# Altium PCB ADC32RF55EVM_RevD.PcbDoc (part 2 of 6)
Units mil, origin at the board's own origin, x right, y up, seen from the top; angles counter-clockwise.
Board outline 4190 x 2750 mil, 14 copper layers (Top Copper, Layer 2 (GND1), Layer 3 (PWR1), Layer 4 (GND2, Layer 5 (PWR2), Layer 6 (GND3), Layer 7 (SIG1), Layer 8 (GND4), Layer 9 (GND5), Layer 10 (SIG2), Layer 11 (GND6), Layer 12 (PWR3), Layer 13 (GND7), Bottom Copper), stack 58.6 mil thick; 427 components, 558 nets, 1902 pads, 1008 vias.
Unrouted connection lines stored in the file: 51.
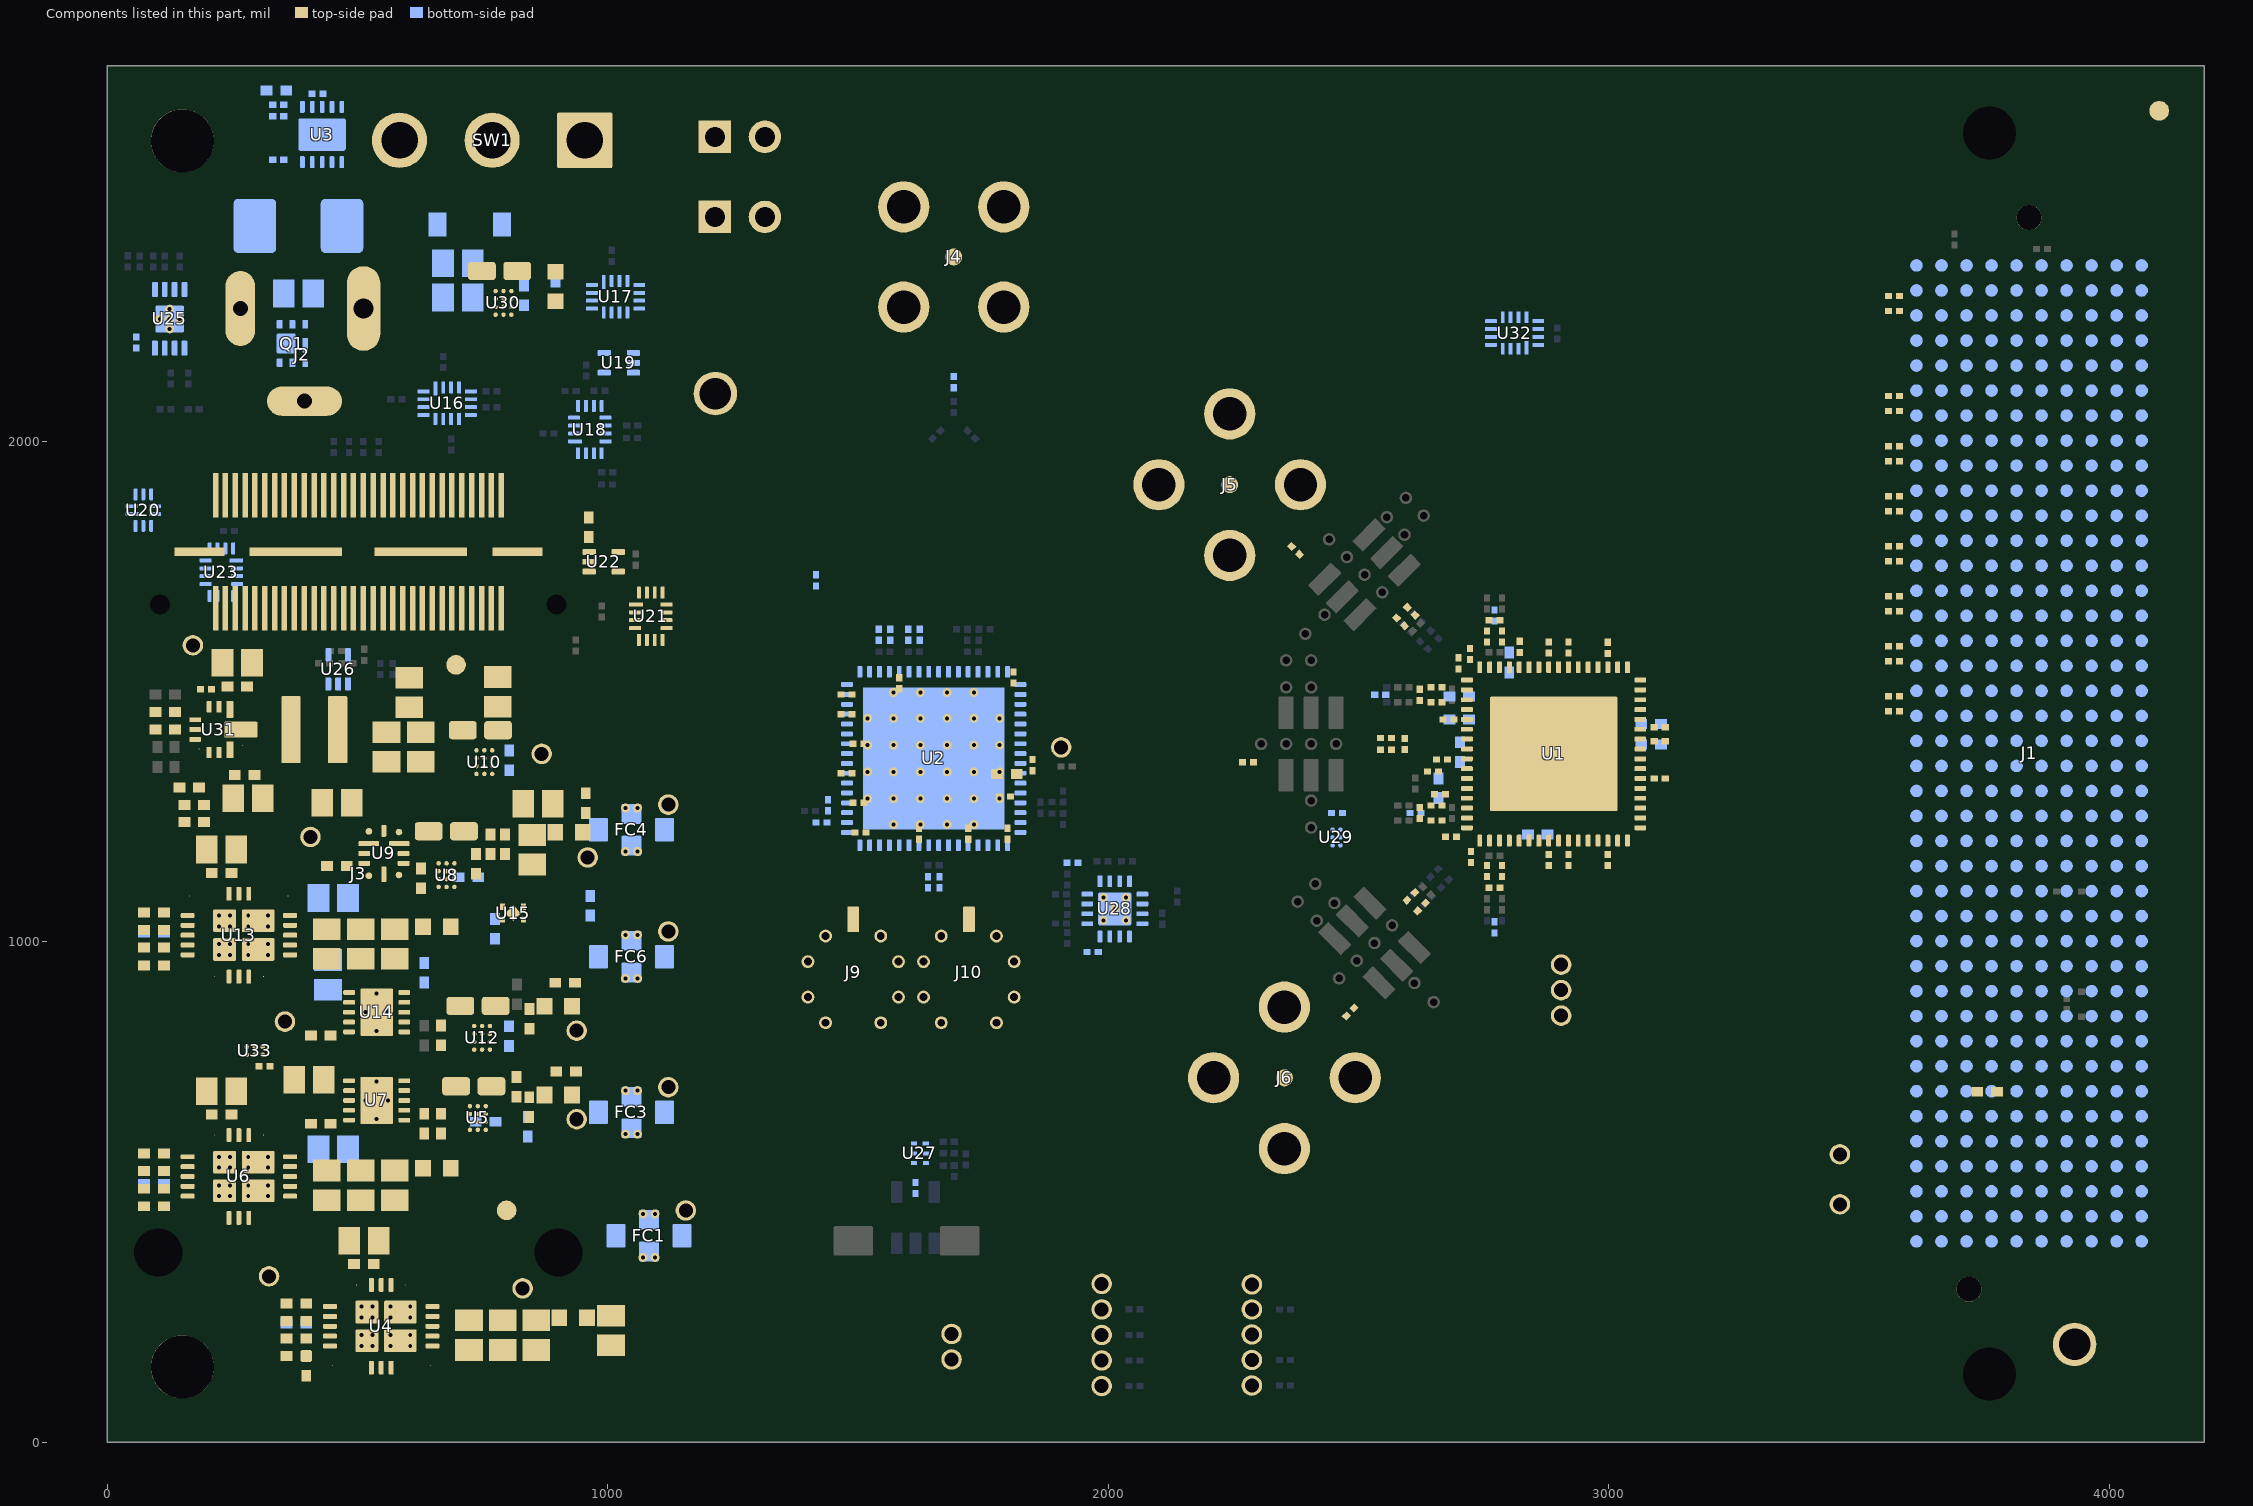
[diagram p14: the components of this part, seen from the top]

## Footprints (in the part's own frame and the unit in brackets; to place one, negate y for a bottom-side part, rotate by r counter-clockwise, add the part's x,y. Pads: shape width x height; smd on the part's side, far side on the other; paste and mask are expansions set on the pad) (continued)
DQK0006C [mm] "WSON"
  rrect50% 0.7x0.29 on Bottom Paste: 0(0.095,-0.65)
  rrect50% 0.9x0.86 on Bottom Paste: 0_1(0,0.325)
  rrect33% 0.45x0.3 smd: 1(-0.975,0.65) 2(-0.975,0) 3(-0.975,-0.65) 4(0.975,-0.65) 5(0.975,0) 6(0.975,0.65)
  rrect33% 0.75x0.3 smd paste-0.15: 7(0.095,-0.65)
  rrect11% 1x0.95 smd paste-0.5: 8(0,0.325)
  silkscreen extent -1.15,-1.15 1.15,1.15, body extent -1,-1 1,1, height 0.82
DQN0004A [mm]
  rect 0.25x0.31 smd paste-0.142 mask-0.14: 1(-0.535,0.325) 2(-0.535,-0.325) 3(0.535,-0.325) 4(0.535,0.325)
  rect 0.58x0.58 smd rot 45 paste-0.065 mask-0.051: 5(0,0)
  Top Copper region: 0.66,0.17 0.66,0.48 0.2,0.48 0.2,0.379 0.409,0.17
  Top Copper region: 0.66,-0.17 0.66,-0.48 0.2,-0.48 0.2,-0.379 0.409,-0.17
  Top Copper region: -0.66,-0.17 -0.66,-0.48 -0.2,-0.48 -0.2,-0.379 -0.409,-0.17
  Top Copper region: -0.66,0.17 -0.66,0.48 -0.2,0.48 -0.2,0.379 -0.409,0.17
  silkscreen extent -1.43,-0.7 0.88,0.7, body extent -0.5,-0.5 0.5,0.5, height 0.37
DRC0010J [mm] "VSON-10"
  rrect42% 0.6x0.24 smd: 1(-1.4,1) 2(-1.4,0.5) 3(-1.4,0) 4(-1.4,-0.5) 5(-1.4,-1) 6(1.4,-1) 7(1.4,-0.5) 8(1.4,0) 9(1.4,0.5) 10(1.4,1)
  rrect12% 1.65x2.4 smd paste-1 mask-2: 11(0,0)
  Top Copper region: -0.375,-1.65 -0.375,-1.2 -0.775,-1.2 -0.785,-1.2 -0.803,-1.192 -0.817,-1.178 -0.825,-1.16 -0.825,-1.15 -0.825,-1.15 -0.825,1.15 -0.825,1.16 -0.817,1.178 -0.803,1.192 -0.785,1.2 -0.775,1.2 -0.775,1.2 -0.375,1.2 -0.375,1.65 -0.375,1.66 -0.367,1.678 -0.353,1.692 -0.335,1.7 -0.325,1.7 -0.325,1.7 -0.325,1.7 -0.175,1.7 -0.165,1.7 -0.147,1.692 -0.133,1.678 -0.125,1.66 -0.125,1.65 -0.125,1.65 -0.125,1.2 0.125,1.2 0.125,1.65 0.125,1.66 0.133,1.678 0.147,1.692 0.165,1.7 0.175,1.7 0.175,1.7 0.175,1.7 0.325,1.7 0.335,1.7 0.353,1.692 0.367,1.678 0.375,1.66 0.375,1.65 0.375,1.65 0.375,1.2 0.775,1.2 0.785,1.2 0.803,1.192 0.817,1.178 0.825,1.16 0.825,1.15 0.825,1.15 0.825,-1.15 0.825,-1.16 0.817,-1.178 0.803,-1.192 0.785,-1.2 0.775,-1.2 0.775,-1.2 0.375,-1.2 0.375,-1.65 0.375,-1.66 0.367,-1.678 0.353,-1.692 0.335,-1.7 0.325,-1.7 0.325,-1.7 0.175,-1.7 0.165,-1.7 0.147,-1.692 0.133,-1.678 0.125,-1.66 0.125,-1.65 0.125,-1.65 0.125,-1.2 -0.125,-1.2 -0.125,-1.65 -0.125,-1.66 -0.133,-1.678 -0.147,-1.692 -0.165,-1.7 -0.175,-1.7 -0.175,-1.7 -0.325,-1.7 -0.335,-1.7 -0.353,-1.692 -0.367,-1.678 -0.375,-1.66 -0.375,-1.65
  body extent -1.5,-1.5 1.5,1.5, height 1
DRL0005A [mm] "SOTFL, 5-Flat Leads, Body 1.2x1.6x0.6mm, Pitch 0.5mm, TI recommended"
  rrect33% 0.67x0.3 smd mask+0.05: 1(-0.74,0.5) 2(-0.74,0) 3(-0.74,-0.5) 4(0.74,-0.5) 5(0.74,0.5)
  silkscreen extent -0.9,-0.95 0.5,0.95, body extent -0.8,-0.8 0.8,0.8, height 0.6
DRY0006A [mm]
  rrect20% 0.35x0.2 smd mask+0.05: 1(-0.298,0.5)
  rrect20% 0.3x0.2 smd mask+0.05: 2(-0.303,0) 3(-0.303,-0.5) 4(0.303,-0.5) 5(0.303,0) 6(0.303,0.5)
  silkscreen extent -0.76,0.64 -0.71,0.69, body extent -0.5,-0.72 0.5,0.72, height 0.6
DSC0010 [mm]
  rrect50% 0.6x0.24 smd paste+0 mask+0.07: 1(-1.4,1) 2(-1.4,0.5) 3(-1.4,0) 4(-1.4,-0.5) 5(-1.4,-1) 6(1.4,-1) 7(1.4,-0.5) 8(1.4,0) 9(1.4,0.5) 10(1.4,1)
  round 0.454 hole 0.2 mask+0.05: 11(-0.575,0) 11(0,-0.95) 11(0,0.95) 11(0.575,0)
  rrect6% 1.65x2.4 smd paste-1000 mask+0: 11(0,0)
  silkscreen extent -1.93,-1.55 1.55,1.55, body extent -1.8,-1.8 1.8,1.8, height 0.25
FCC_disclaimer [mil]
Fiducial10-20 [mm]
  round 1 smd paste-0.508 mask+0.203: 1(0,0)
FP-1101M2S3CGE2_SIP3-MFG [mm]
  rrect4% 2.8x2.8 hole 1.85 paste-2539.97 mask+0: 1(0,4.7)
  round 2.8 hole 1.85 paste-2539.97 mask+0: 2(0,0) 3(0,-4.7)
  silkscreen extent -3.3,-6.35 3.3,6.35, body extent -3.4,-6.45 3.4,6.45, height 0.25
FP-2116-440-AL_STANDOFF_HEX_1-4-MFG [mm]
  round 3.2 hole 3.2 unplated paste-2539.97 mask+0: ""(0,0)
  body extent -3.66,-3.18 3.66,3.18, height 31.88
FP-132134-15_CONN_SMA_JACK-MFG [mm]
  round 0.864 smd paste+0 mask+0: 1(0,0)
  round 2.6 hole 1.7 paste-2539.97 mask+0: 2(-2.54,2.54) 3(2.54,2.54) 4(-2.54,-2.54) 5(2.54,-2.54)
  silkscreen extent -3.6,-3.6 3.6,3.6, body extent -3.94,-3.94 3.94,3.94, height 0.25
FTDI_Dongle_001 [mm]
  rect 2.27x0.279 smd: 1(18.74,-7.25) 2(13.01,-7.25) 3(18.74,-6.75) 4(13.01,-6.75) 5(18.74,-6.25) 6(13.01,-6.25) 7(18.74,-5.75) 8(13.01,-5.75) 9(18.74,-5.25) 10(13.01,-5.25) 11(18.74,-4.75) 12(13.01,-4.75) 13(18.74,-4.25) 14(13.01,-4.25) 15(18.74,-3.75) 16(13.01,-3.75) 17(18.74,-3.25) 18(13.01,-3.25) 19(18.74,-2.75) 20(13.01,-2.75) 21(18.74,-2.25) 22(13.01,-2.25) 23(18.74,-1.75) 24(13.01,-1.75) 25(18.74,-1.25) 26(13.01,-1.25) 27(18.74,-0.75) 28(13.01,-0.75) 29(18.74,-0.25) 30(13.01,-0.25) 31(18.74,0.25) 32(13.01,0.25) 33(18.74,0.75) 34(13.01,0.75) 35(18.74,1.25) 36(13.01,1.25) 37(18.74,1.75) 38(13.01,1.75) 39(18.74,2.25) 40(13.01,2.25) 41(18.74,2.75) 42(13.01,2.75) 43(18.74,3.25) 44(13.01,3.25) 45(18.74,3.75) 46(13.01,3.75) 47(18.74,4.25) 48(13.01,4.25) 49(18.74,4.75) 50(13.01,4.75) 51(18.74,5.25) 52(13.01,5.25) 53(18.74,5.75) 54(13.01,5.75) 55(18.74,6.25) 56(13.01,6.25) 57(18.74,6.75) 58(13.01,6.75) 59(18.74,7.25) 60(13.01,7.25)
  round 2 hole 2.45 unplated: 4(-19.685,-10.16) 4(-19.685,10.16)
  round 0 hole 1.02 unplated: MH1(13.205,-10.065) MH2(13.205,10.065)
  rect 0.43x2.54 smd: MP1(15.875,-8.065) MP4(15.875,8.065)
  rect 0.43x4.7 smd: MP2(15.875,-3.175) MP3(15.875,3.175)
  silkscreen extent 12.26,-10.66 19.78,10.65, body extent -22.78,-12.7 22.22,12.7, height 10.54
Keystone5011 [mil] "Keystone Multipurpose loops"
  round 87 hole 63: 1(0,0)
  silkscreen extent -70,-70 70,70, body extent -63,-63 63,62, height 319
Label_650x200 [mil] "Thermal Transfer Label"
  round 1 on Mech13: 0(0,0)
  silkscreen extent -325,-100 325,100, body extent -325,-100 325,100, height 1
LED_LTST-C190-Green [mm] "Lite-On"
  rect 0.8x0.8 smd: 1(-0.75,0) 2(0.75,0)
  silkscreen extent -1.1,-0.8 1.8,0.8, body extent -0.85,-0.45 0.85,0.45, height 0.91
MMCNYN256 [mil] "Nylon Hex Nut 2-56"
  body extent -94,-108 94,108, height 256
Molex_0853050232 [mm] "Plug, 50 Ohm, Straight, SMT"
  rrect17% 0.6x1.3 smd: 1(0,0)
  round 0.654 hole 0.4 mask+0.05: 2(-2.3,-3.95) 2(-2.3,-2.15) 2(-1.4,-0.85) 2(-1.4,-5.25) 2(1.4,-5.25) 2(1.4,-0.85) 2(2.3,-3.95) 2(2.3,-2.15)
  round 0.025 smd: 2(0,-5.35)
  Top Copper pour cut-out: 0.998,-1.315 0.998,-0.45 -0.998,-0.45 -0.998,-1.321 -1.679,-1.973 -1.986,-2.865 -1.849,-3.798 -1.3,-4.565 -0.461,-4.995 0.482,-4.992 1.319,-4.557 1.864,-3.787 1.995,-2.854 1.683,-1.963 0.998,-1.315
  Top Copper pour cut-out: -0.33,0.699 -0.33,-0.698 0.33,-0.698 0.33,0.699
  Top Copper region: -2.6,-5.65 -2.6,-0.45 -1,-0.45 -1,-1.318 -1.732,-2.05 -2,-3.05 -1.732,-4.05 -1,-4.782 0,-5.05 1,-4.782 1.732,-4.05 2,-3.05 1.732,-2.05 1,-1.318 1,-1.318 1,-0.45 2.6,-0.45 2.6,-5.65
  Layer 2 (GND1) pour cut-out: 0.998,-1.315 0.998,-0.45 -0.998,-0.45 -0.998,-1.321 -1.679,-1.973 -1.986,-2.865 -1.849,-3.798 -1.3,-4.565 -0.461,-4.995 0.482,-4.992 1.319,-4.557 1.864,-3.787 1.995,-2.854 1.683,-1.963 0.998,-1.315
  Layer 2 (GND1) pour cut-out: 0.998,-1.315 0.998,-0.45 -0.998,-0.45 -0.998,-1.321 -1.679,-1.973 -1.986,-2.865 -1.849,-3.798 -1.3,-4.565 -0.461,-4.995 0.482,-4.992 1.319,-4.557 1.864,-3.787 1.995,-2.854 1.683,-1.963 0.998,-1.315
  Layer 2 (GND1) pour cut-out: 0.998,-1.315 0.998,-0.45 -0.998,-0.45 -0.998,-1.321 -1.679,-1.973 -1.986,-2.865 -1.849,-3.798 -1.3,-4.565 -0.461,-4.995 0.482,-4.992 1.319,-4.557 1.864,-3.787 1.995,-2.854 1.683,-1.963 0.998,-1.315
  Layer 2 (GND1) pour cut-out: -0.33,0.699 -0.33,-0.698 0.33,-0.698 0.33,0.699
  body extent -2.5,-5.55 2.5,0.45, height 4.1
NFM31PC [mm]
  rrect10% 0.95x1.2 smd paste+0: 1(-1.675,0) 3(1.675,0)
  round 0.2 / inner round 0.454 / far side round 0.454 hole 0.2 mask+0.05: 2(-0.305,-1.105) 2(-0.305,1.105) 2(0.305,-1.105) 2(0.305,1.105)
  rrect10% 1x1 smd paste+0: 2(0,-0.8) 2(0,0.8)
  body extent -1.7,-0.9 1.7,0.9, height 1.5
NKD0064A [mm] "QFN, 64-Leads, Body 9x9mm, Pitch 0.5mm"
  rrect40% 0.6x0.25 smd mask+0.07: 1(-4.4,3.75) 2(-4.4,3.25) 3(-4.4,2.75) 4(-4.4,2.25) 5(-4.4,1.75) 6(-4.4,1.25) 7(-4.4,0.75) 8(-4.4,0.25) 9(-4.4,-0.25) 10(-4.4,-0.75) 11(-4.4,-1.25) 12(-4.4,-1.75) 13(-4.4,-2.25) 14(-4.4,-2.75) 15(-4.4,-3.25) 16(-4.4,-3.75) 33(4.4,-3.75) 34(4.4,-3.25) 35(4.4,-2.75) 36(4.4,-2.25) 37(4.4,-1.75) 38(4.4,-1.25) 39(4.4,-0.75) 40(4.4,-0.25) 41(4.4,0.25) 42(4.4,0.75) 43(4.4,1.25) 44(4.4,1.75) 45(4.4,2.25) 46(4.4,2.75) 47(4.4,3.25) 48(4.4,3.75)
  rrect40% 0.25x0.6 smd mask+0.07: 17(-3.75,-4.4) 18(-3.25,-4.4) 19(-2.75,-4.4) 20(-2.25,-4.4) 21(-1.75,-4.4) 22(-1.25,-4.4) 23(-0.75,-4.4) 24(-0.25,-4.4) 25(0.25,-4.4) 26(0.75,-4.4) 27(1.25,-4.4) 28(1.75,-4.4) 29(2.25,-4.4) 30(2.75,-4.4) 31(3.25,-4.4) 32(3.75,-4.4) 49(3.75,4.4) 50(3.25,4.4) 51(2.75,4.4) 52(2.25,4.4) 53(1.75,4.4) 54(1.25,4.4) 55(0.75,4.4) 56(0.25,4.4) 57(-0.25,4.4) 58(-0.75,4.4) 59(-1.25,4.4) 60(-1.75,4.4) 61(-2.25,4.4) 62(-2.75,4.4) 63(-3.25,4.4) 64(-3.75,4.4)
  round 0.454 hole 0.2 mask+0.102: 65(-3.35,-2.04) 65(-3.35,-0.68) 65(-3.35,0.68) 65(-3.35,2.04) 65(-2.04,-3.35) 65(-2.04,-2.04) 65(-2.04,-0.68) 65(-2.04,0.68) 65(-2.04,2.04) 65(-2.04,3.35) 65(-0.68,-3.35) 65(-0.68,-2.04) 65(-0.68,-0.68) 65(-0.68,0.68) 65(-0.68,2.04) 65(-0.68,3.35) 65(0.68,-3.35) 65(0.68,-2.04) 65(0.68,-0.68) 65(0.68,0.68) 65(0.68,2.04) 65(0.68,3.35) 65(2.04,-3.35) 65(2.04,-2.04) 65(2.04,-0.68) 65(2.04,0.68) 65(2.04,2.04) 65(2.04,3.35) 65(3.35,-2.04) 65(3.35,-0.68) 65(3.35,0.68) 65(3.35,2.04)
  rrect1% 7.2x7.2 smd paste-3.6 mask+0.07: 65(0,0)
  silkscreen extent -4.65,-4.65 4.65,4.65, body extent -4.55,-4.55 4.55,4.55, height 0.81
PBC02SAAN [mm] "Sullins 100mil, 1x2, 230 mil above insulator"
  rect 1.65x1.65 hole 1.016: 1(0,1.27)
  round 1.65 hole 1.016: 2(0,-1.27)
  silkscreen extent -1.27,-2.54 1.6,2.54, body extent -1.27,-2.54 1.27,2.54, height 8.38
ProbePoint_TH_40mil [mil]
  round 41 hole 28: 1(0,0)
RAPC722X [mm] "Conn_DC Jack"
  oval 1.7x4.3 hole 1.01 slot 3.56 at 90 deg: 1(14.194,0)
  oval 1.5x3.8 hole 0.76 slot 3.05 at 90 deg: 2(7.946,0)
  oval 3.8x1.5 hole 0.76 slot 3.05 at 0 deg: 3(11.197,-4.7)
  silkscreen extent 0.2,-4.57 14.93,4.57, body extent 0.58,-4.97 15.06,4.56, height 10.92
RDU0028A [mm]
  round 0.025 smd mask+0.05: 1(-1.987,2.487) 2(-2.1,1.25) 6(-2.1,-1.25) 7(-1.987,-2.488) 13(1.987,-2.488) 14(2.1,-1.25) 18(2.1,1.25) 19(1.988,2.488)
  rrect40% 0.7x0.25 smd paste+0 mask+0.05: 3(-2.1,0.5) 4(-2.1,0) 5(-2.1,-0.5) 15(2.1,-0.5) 16(2.1,0) 17(2.1,0.5)
  rrect40% 0.25x0.7 smd paste+0 mask+0.05: 8(-1,-2.6) 9(-0.5,-2.6) 10(0,-2.6) 11(0.5,-2.6) 12(1,-2.6) 20(1,2.6) 21(0.5,2.6) 22(0,2.6) 23(-0.5,2.6) 24(-1,2.6)
  round 0.454 hole 0.2 mask+0.102: 25(-1,1) 25(-1,0.45) 25(-0.45,1) 25(-0.45,0.45) 26(-1,-0.475) 26(-1,-1.475) 26(-0.45,-0.475) 26(-0.45,-1.475) 27(0.45,-0.475) 27(0.45,-1.475) 27(1,-0.475) 27(1,-1.475) 28(0.45,1) 28(0.45,0.45) 28(1,1) 28(1,0.45)
  rrect9% 1.15x1.15 smd paste-1000 mask+0.05: 25(-0.725,0.725) 28(0.725,0.725)
  rrect9% 1.15x1.65 smd paste-1000 mask+0.05: 26(-0.725,-0.975) 27(0.725,-0.975)
  Top Copper region: 1.575,2.95 1.55,2.943 1.532,2.925 1.525,2.9 1.525,2.9 1.525,2.075 1.529,2.056 1.54,2.04 1.556,2.029 1.575,2.025 1.575,2.025 2.4,2.025 2.423,2.033 2.439,2.051 2.445,2.075 2.445,2.075 2.45,2.225 2.443,2.25 2.425,2.268 2.4,2.275 2.4,2.275 2.225,2.275 2.187,2.283 2.154,2.304 2.133,2.337 2.125,2.375 2.125,2.375 2.125,2.575 2.118,2.6 2.1,2.618 2.075,2.625 2.075,2.625 1.875,2.625 1.837,2.633 1.804,2.654 1.783,2.687 1.775,2.725 1.775,2.725 1.775,2.9 1.768,2.925 1.75,2.943 1.725,2.95 1.725,2.95
  Top Copper region: 2.4,-1.625 1.8,-1.625 1.775,-1.618 1.757,-1.6 1.75,-1.575 1.75,-1.575 1.75,-0.925 1.754,-0.906 1.765,-0.89 1.781,-0.879 1.8,-0.875 1.8,-0.875 2.4,-0.875 2.419,-0.879 2.435,-0.89 2.446,-0.906 2.45,-0.925 2.45,-0.925 2.45,-1.075 2.443,-1.1 2.425,-1.118 2.4,-1.125 2.4,-1.125 2.225,-1.125 2.187,-1.133 2.154,-1.154 2.133,-1.187 2.125,-1.225 2.125,-1.225 2.125,-1.275 2.138,-1.325 2.175,-1.362 2.225,-1.375 2.225,-1.375 2.4,-1.375 2.419,-1.379 2.435,-1.39 2.446,-1.406 2.45,-1.425 2.45,-1.425 2.45,-1.575 2.443,-1.6 2.425,-1.618 2.4,-1.625
  Top Copper region: 1.575,-2.95 1.55,-2.943 1.532,-2.925 1.525,-2.9 1.525,-2.9 1.525,-2.075 1.529,-2.056 1.54,-2.04 1.556,-2.029 1.575,-2.025 1.575,-2.025 2.4,-2.025 2.423,-2.033 2.439,-2.051 2.445,-2.075 2.445,-2.075 2.45,-2.225 2.443,-2.25 2.425,-2.268 2.4,-2.275 2.4,-2.275 2.225,-2.275 2.187,-2.283 2.154,-2.304 2.133,-2.337 2.125,-2.375 2.125,-2.375 2.125,-2.575 2.118,-2.6 2.1,-2.618 2.075,-2.625 2.075,-2.625 1.875,-2.625 1.837,-2.633 1.804,-2.654 1.783,-2.687 1.775,-2.725 1.775,-2.725 1.775,-2.9 1.768,-2.925 1.75,-2.943 1.725,-2.95 1.725,-2.95
  Top Copper region: -1.575,2.95 -1.55,2.943 -1.532,2.925 -1.525,2.9 -1.525,2.9 -1.525,2.075 -1.529,2.056 -1.54,2.04 -1.556,2.029 -1.575,2.025 -1.575,2.025 -2.4,2.025 -2.423,2.033 -2.439,2.051 -2.445,2.075 -2.445,2.075 -2.45,2.225 -2.443,2.25 -2.425,2.268 -2.4,2.275 -2.4,2.275 -2.225,2.275 -2.187,2.283 -2.154,2.304 -2.133,2.337 -2.125,2.375 -2.125,2.375 -2.125,2.575 -2.118,2.6 -2.1,2.618 -2.075,2.625 -2.075,2.625 -1.875,2.625 -1.837,2.633 -1.804,2.654 -1.783,2.687 -1.775,2.725 -1.775,2.725 -1.775,2.9 -1.768,2.925 -1.75,2.943 -1.725,2.95 -1.725,2.95
  Top Copper region: -1.575,-2.95 -1.55,-2.943 -1.532,-2.925 -1.525,-2.9 -1.525,-2.9 -1.525,-2.075 -1.529,-2.056 -1.54,-2.04 -1.556,-2.029 -1.575,-2.025 -1.575,-2.025 -2.4,-2.025 -2.423,-2.033 -2.439,-2.051 -2.445,-2.075 -2.445,-2.075 -2.45,-2.225 -2.443,-2.25 -2.425,-2.268 -2.4,-2.275 -2.4,-2.275 -2.225,-2.275 -2.187,-2.283 -2.154,-2.304 -2.133,-2.337 -2.125,-2.375 -2.125,-2.375 -2.125,-2.575 -2.118,-2.6 -2.1,-2.618 -2.075,-2.625 -2.075,-2.625 -1.875,-2.625 -1.837,-2.633 -1.804,-2.654 -1.783,-2.687 -1.775,-2.725 -1.775,-2.725 -1.775,-2.9 -1.768,-2.925 -1.75,-2.943 -1.725,-2.95 -1.725,-2.95
  Top Copper region: -2.4,-0.875 -1.8,-0.875 -1.775,-0.882 -1.757,-0.9 -1.75,-0.925 -1.75,-0.925 -1.75,-1.575 -1.754,-1.594 -1.765,-1.61 -1.781,-1.621 -1.8,-1.625 -1.8,-1.625 -2.4,-1.625 -2.419,-1.621 -2.435,-1.61 -2.446,-1.594 -2.45,-1.575 -2.45,-1.575 -2.45,-1.425 -2.443,-1.4 -2.425,-1.382 -2.4,-1.375 -2.4,-1.375 -2.225,-1.375 -2.187,-1.367 -2.154,-1.346 -2.133,-1.313 -2.125,-1.275 -2.125,-1.275 -2.125,-1.225 -2.138,-1.175 -2.175,-1.138 -2.225,-1.125 -2.225,-1.125 -2.4,-1.125 -2.419,-1.121 -2.435,-1.11 -2.446,-1.094 -2.45,-1.075 -2.45,-1.075 -2.45,-0.925 -2.443,-0.9 -2.425,-0.882 -2.4,-0.875
  Top Copper region: -2.4,1.625 -1.8,1.625 -1.781,1.621 -1.765,1.61 -1.754,1.594 -1.75,1.575 -1.75,1.575 -1.75,0.925 -1.754,0.906 -1.765,0.89 -1.781,0.879 -1.8,0.875 -1.8,0.875 -2.4,0.875 -2.419,0.879 -2.435,0.89 -2.446,0.906 -2.45,0.925 -2.45,0.925 -2.45,1.075 -2.443,1.1 -2.425,1.118 -2.4,1.125 -2.4,1.125 -2.225,1.125 -2.187,1.133 -2.154,1.154 -2.133,1.187 -2.125,1.225 -2.125,1.225 -2.125,1.275 -2.138,1.325 -2.175,1.362 -2.225,1.375 -2.225,1.375 -2.4,1.375 -2.419,1.379 -2.435,1.39 -2.446,1.406 -2.45,1.425 -2.45,1.425 -2.45,1.575 -2.443,1.6 -2.425,1.618 -2.4,1.625
  Top Copper region: 2.4,0.875 1.8,0.875 1.775,0.882 1.757,0.9 1.75,0.925 1.75,0.925 1.75,1.575 1.754,1.594 1.765,1.61 1.781,1.621 1.8,1.625 1.8,1.625 2.4,1.625 2.419,1.621 2.435,1.61 2.446,1.594 2.45,1.575 2.45,1.575 2.45,1.425 2.443,1.4 2.425,1.382 2.4,1.375 2.4,1.375 2.225,1.375 2.187,1.367 2.154,1.346 2.133,1.313 2.125,1.275 2.125,1.275 2.125,1.225 2.138,1.175 2.175,1.138 2.225,1.125 2.225,1.125 2.4,1.125 2.419,1.121 2.435,1.11 2.446,1.094 2.45,1.075 2.45,1.075 2.45,0.925 2.443,0.9 2.425,0.882 2.4,0.875
  silkscreen extent -3.2,-3.13 2.63,3.13, body extent -2.55,-3.05 2.55,3.05, height 0.25
RGT0016C [mm]
  rrect30% 0.6x0.24 smd paste+0 mask+0.07: 1(-1.4,0.75) 2(-1.4,0.25) 3(-1.4,-0.25) 4(-1.4,-0.75) 9(1.4,-0.75) 10(1.4,-0.25) 11(1.4,0.25) 12(1.4,0.75)
  rrect30% 0.24x0.6 smd paste+0 mask+0.07: 5(-0.75,-1.4) 6(-0.25,-1.4) 7(0.25,-1.4) 8(0.75,-1.4) 13(0.75,1.4) 14(0.25,1.4) 15(-0.25,1.4) 16(-0.75,1.4)
  round 0.454 hole 0.2 mask+0.05: 17(-0.58,-0.58) 17(-0.58,0.58) 17(0,0) 17(0.58,-0.58) 17(0.58,0.58)
  rrect10% 1.68x1.68 smd paste-0.065 mask+0.07: 17(0,0)
  silkscreen extent -1.97,-1.68 1.68,1.68, body extent -1.5,-1.5 1.5,1.5, height 1
RPS0012A-MFG [mm]
  round 0.34 smd paste+0 mask+0: 1(-0.761,1.127) 5(-0.761,-1.127)
  rrect40% 1.05x0.25 smd paste+0 mask+0: 2(-0.775,0.5) 10(0.775,0.5)
  rrect40% 0.6x0.25 smd paste+0 mask+0: 3(-1,0) 4(-1,-0.5) 8(1,-0.5) 9(1,0)
  rrect40% 0.25x0.8 smd paste+0 mask+0: 6(0,-1.05)
  round 0.332 smd paste+0 mask+0: 7(0.766,-1.091) 11(0.766,1.091)
  rrect40% 0.25x0.6 smd paste+0 mask+0: 12(0,1.15)
  Top Copper region: 1.25,-1.1 0.95,-1.1 0.95,-1.4 0.95,-1.41 0.942,-1.428 0.928,-1.442 0.91,-1.45 0.9,-1.45 0.9,-1.45 0.6,-1.45 0.59,-1.45 0.572,-1.442 0.558,-1.428 0.55,-1.41 0.55,-1.4 0.55,-1.4 0.55,-0.925 0.55,-0.915 0.558,-0.897 0.572,-0.883 0.59,-0.875 0.6,-0.875 0.6,-0.875 1.25,-0.875 1.26,-0.875 1.278,-0.883 1.292,-0.897 1.3,-0.915 1.3,-0.925 1.3,-0.925 1.3,-1.05 1.3,-1.06 1.292,-1.078 1.278,-1.092 1.26,-1.1 1.25,-1.1
  Top Copper region: -1.25,-1.1 -0.95,-1.1 -0.95,-1.4 -0.95,-1.41 -0.942,-1.428 -0.928,-1.442 -0.91,-1.45 -0.9,-1.45 -0.9,-1.45 -0.6,-1.45 -0.59,-1.45 -0.572,-1.442 -0.558,-1.428 -0.55,-1.41 -0.55,-1.4 -0.55,-1.4 -0.55,-0.925 -0.55,-0.915 -0.558,-0.897 -0.572,-0.883 -0.59,-0.875 -0.6,-0.875 -0.6,-0.875 -1.25,-0.875 -1.26,-0.875 -1.278,-0.883 -1.292,-0.897 -1.3,-0.915 -1.3,-0.925 -1.3,-0.925 -1.3,-1.05 -1.3,-1.06 -1.292,-1.078 -1.278,-1.092 -1.26,-1.1 -1.25,-1.1
  Top Copper region: -1.25,1.1 -0.95,1.1 -0.95,1.4 -0.95,1.41 -0.942,1.428 -0.928,1.442 -0.91,1.45 -0.9,1.45 -0.9,1.45 -0.6,1.45 -0.59,1.45 -0.572,1.442 -0.558,1.428 -0.55,1.41 -0.55,1.4 -0.55,1.4 -0.55,0.925 -0.55,0.915 -0.558,0.897 -0.572,0.883 -0.59,0.875 -0.6,0.875 -0.6,0.875 -1.25,0.875 -1.26,0.875 -1.278,0.883 -1.292,0.897 -1.3,0.915 -1.3,0.925 -1.3,0.925 -1.3,1.05 -1.3,1.06 -1.292,1.078 -1.278,1.092 -1.26,1.1 -1.25,1.1
  Top Copper region: 1.25,1.1 0.95,1.1 0.95,1.4 0.95,1.41 0.942,1.428 0.928,1.442 0.91,1.45 0.9,1.45 0.9,1.45 0.6,1.45 0.59,1.45 0.572,1.442 0.558,1.428 0.55,1.41 0.55,1.4 0.55,1.4 0.55,0.925 0.55,0.915 0.558,0.897 0.572,0.883 0.59,0.875 0.6,0.875 0.6,0.875 1.25,0.875 1.26,0.875 1.278,0.883 1.292,0.897 1.3,0.915 1.3,0.925 1.3,0.925 1.3,1.05 1.3,1.06 1.292,1.078 1.278,1.092 1.26,1.1 1.25,1.1
  silkscreen extent -1.41,-1.8 1.3,2.29, body extent -1.1,-1.25 1.1,1.25, height 1
RPY0014A [mm]
  round 0.025 smd mask+0.05: 1(-1.213,0.987) 5(-1.212,-0.988) 9(0.975,-0.8) 11(0.975,0.8)
  rrect20% 0.575x0.25 smd paste+0 mask+0.05: 2(-1.412,0.5) 3(-1.412,0) 4(-1.412,-0.5)
  rrect20% 0.25x0.575 smd paste+0 mask+0.05: 6(-0.7,-1.162) 7(-0.2,-1.162) 13(-0.2,1.162) 14(-0.7,1.162)
  rrect10% 0.35x0.851 smd paste+0 mask+0.05: 8(0.35,-1.025) 12(0.35,1.025)
  rrect10% 1.675x0.8 smd paste-0.825 mask-0.826: 10(0.913,0)
  Top Copper region: 1.237,0.6 1.65,0.6 1.669,0.604 1.685,0.615 1.696,0.631 1.7,0.65 1.7,0.65 1.7,0.95 1.696,0.969 1.685,0.985 1.669,0.996 1.65,1 1.65,1 1.175,1 1.175,1.4 1.175,1.4 1.175,1.4 1.171,1.419 1.16,1.435 1.144,1.446 1.125,1.45 1.125,1.45 0.82,1.45 0.803,1.447 0.788,1.437 0.778,1.422 0.775,1.405 0.775,1.405 0.775,0.64 0.778,0.625 0.787,0.612 0.8,0.603 0.815,0.6 0.815,0.6 0.874,0.6
  Top Copper region: 1.237,-0.6 1.65,-0.6 1.669,-0.604 1.685,-0.615 1.696,-0.631 1.7,-0.65 1.7,-0.65 1.7,-0.95 1.696,-0.969 1.685,-0.985 1.669,-0.996 1.65,-1 1.65,-1 1.175,-1 1.175,-1.4 1.175,-1.4 1.175,-1.4 1.171,-1.419 1.16,-1.435 1.144,-1.446 1.125,-1.45 1.125,-1.45 0.82,-1.45 0.803,-1.447 0.788,-1.437 0.778,-1.422 0.775,-1.405 0.775,-1.405 0.775,-0.64 0.778,-0.625 0.787,-0.612 0.8,-0.603 0.815,-0.6 0.815,-0.6 0.874,-0.6
  Top Copper region: -1.115,0.875 -1.1,0.878 -1.087,0.887 -1.078,0.9 -1.075,0.915 -1.075,0.915 -1.075,1.4 -1.075,1.4 -1.075,1.405 -1.078,1.422 -1.088,1.437 -1.103,1.447 -1.12,1.45 -1.12,1.45 -1.3,1.45 -1.319,1.446 -1.335,1.435 -1.346,1.419 -1.35,1.4 -1.35,1.4 -1.35,1.1 -1.655,1.1 -1.672,1.097 -1.687,1.087 -1.697,1.072 -1.7,1.055 -1.7,1.055 -1.7,0.915 -1.697,0.9 -1.688,0.887 -1.675,0.878 -1.66,0.875 -1.66,0.875
  Top Copper region: -1.115,-0.875 -1.1,-0.878 -1.087,-0.887 -1.078,-0.9 -1.075,-0.915 -1.075,-0.915 -1.075,-1.4 -1.075,-1.4 -1.075,-1.405 -1.078,-1.422 -1.088,-1.437 -1.103,-1.447 -1.12,-1.45 -1.12,-1.45 -1.3,-1.45 -1.319,-1.446 -1.335,-1.435 -1.346,-1.419 -1.35,-1.4 -1.35,-1.4 -1.35,-1.1 -1.655,-1.1 -1.672,-1.097 -1.687,-1.087 -1.696,-1.072 -1.7,-1.055 -1.7,-1.055 -1.7,-0.915 -1.697,-0.9 -1.688,-0.887 -1.675,-0.878 -1.66,-0.875 -1.66,-0.875
  silkscreen extent -2.4,-1.63 1.92,1.63, body extent -1.5,-1.25 1.5,1.25, height 1.01
RSV0016A [mm] "QFN, 16-Leads, Body 1.8x2.6mm, Pitch 0.4mm, TI Recommended"
  rrect25% 0.7x0.2 smd mask+0.05: 1(-0.75,0.6)
  rrect25% 0.6x0.2 smd mask+0.05: 2(-0.8,0.2) 3(-0.8,-0.2) 4(-0.8,-0.6) 9(0.8,-0.6) 10(0.8,-0.2) 11(0.8,0.2) 12(0.8,0.6)
  rrect25% 0.2x0.6 smd mask+0.05: 5(-0.6,-1.2) 6(-0.2,-1.2) 7(0.2,-1.2) 8(0.6,-1.2) 13(0.6,1.2) 14(0.2,1.2) 15(-0.2,1.2) 16(-0.6,1.2)
  silkscreen extent -1.08,-1.33 1.08,1.45, body extent -0.93,-1.32 0.92,1.33, height 0.56
RSW0010A [mm]
  rrect50% 0.7x0.2 smd mask+0.05: 1(-0.55,0.2)
  rrect50% 0.6x0.2 smd mask+0.05: 2(-0.6,-0.2) 6(0.6,-0.2) 7(0.6,0.2)
  rrect50% 0.2x0.6 smd mask+0.05: 3(-0.4,-0.8) 4(0,-0.8) 5(0.4,-0.8) 8(0.4,0.8) 9(0,0.8) 10(-0.4,0.8)
  silkscreen extent -0.87,-0.92 0.72,0.93, body extent -0.7,-0.9 0.7,0.9, height 0.55
RTD0064L [mm] "VQFN-64"
  rrect40% 0.6x0.25 smd: 1(-4.4,3.75) 2(-4.4,3.25) 3(-4.4,2.75) 4(-4.4,2.25) 5(-4.4,1.75) 6(-4.4,1.25) 7(-4.4,0.75) 8(-4.4,0.25) 9(-4.4,-0.25) 10(-4.4,-0.75) 11(-4.4,-1.25) 12(-4.4,-1.75) 13(-4.4,-2.25) 14(-4.4,-2.75) 15(-4.4,-3.25) 16(-4.4,-3.75) 33(4.4,-3.75) 34(4.4,-3.25) 35(4.4,-2.75) 36(4.4,-2.25) 37(4.4,-1.75) 38(4.4,-1.25) 39(4.4,-0.75) 40(4.4,-0.25) 41(4.4,0.25) 42(4.4,0.75) 43(4.4,1.25) 44(4.4,1.75) 45(4.4,2.25) 46(4.4,2.75) 47(4.4,3.25) 48(4.4,3.75)
  rrect40% 0.25x0.6 smd: 17(-3.75,-4.4) 18(-3.25,-4.4) 19(-2.75,-4.4) 20(-2.25,-4.4) 21(-1.75,-4.4) 22(-1.25,-4.4) 23(-0.75,-4.4) 24(-0.25,-4.4) 25(0.25,-4.4) 26(0.75,-4.4) 27(1.25,-4.4) 28(1.75,-4.4) 29(2.25,-4.4) 30(2.75,-4.4) 31(3.25,-4.4) 32(3.75,-4.4) 49(3.75,4.4) 50(3.25,4.4) 51(2.75,4.4) 52(2.25,4.4) 53(1.75,4.4) 54(1.25,4.4) 55(0.75,4.4) 56(0.25,4.4) 57(-0.25,4.4) 58(-0.75,4.4) 59(-1.25,4.4) 60(-1.75,4.4) 61(-2.25,4.4) 62(-2.75,4.4) 63(-3.25,4.4) 64(-3.75,4.4)
  rrect2% 5.808x6.466 smd paste-3.5: 65(0,0)
  silkscreen extent -5.83,3.53 -5.13,4.23, body extent -4.5,-4.5 4.5,4.5, height 0.9
SAMTEC_ASP-134488-01 [mm]
  round 0.64 smd far side paste+0.125: A1(24.79,-5.715) A2(23.52,-5.715) A3(22.25,-5.715) A4(20.98,-5.715) A5(19.71,-5.715) A6(18.44,-5.715) A7(17.17,-5.715) A8(15.9,-5.715) A9(14.63,-5.715) A10(13.36,-5.715) A11(12.09,-5.715) A12(10.82,-5.715) A13(9.55,-5.715) A14(8.28,-5.715) A15(7.01,-5.715) A16(5.74,-5.715) A17(4.47,-5.715) A18(3.2,-5.715) A19(1.93,-5.715) A20(0.66,-5.715) A21(-0.61,-5.715) A22(-1.88,-5.715) A23(-3.15,-5.715) A24(-4.42,-5.715) A25(-5.69,-5.715) A26(-6.96,-5.715) A27(-8.23,-5.715) A28(-9.5,-5.715) A29(-10.77,-5.715) A30(-12.04,-5.715) A31(-13.31,-5.715) A32(-14.58,-5.715) A33(-15.85,-5.715) A34(-17.12,-5.715) A35(-18.39,-5.715) A36(-19.66,-5.715) A37(-20.93,-5.715) A38(-22.2,-5.715) A39(-23.47,-5.715) A40(-24.74,-5.715) B1(24.79,-4.445) B2(23.52,-4.445) B3(22.25,-4.445) B4(20.98,-4.445) B5(19.71,-4.445) B6(18.44,-4.445) B7(17.17,-4.445) B8(15.9,-4.445) B9(14.63,-4.445) B10(13.36,-4.445) B11(12.09,-4.445) B12(10.82,-4.445) B13(9.55,-4.445) B14(8.28,-4.445) B15(7.01,-4.445) B16(5.74,-4.445) B17(4.47,-4.445) B18(3.2,-4.445) B19(1.93,-4.445) B20(0.66,-4.445) B21(-0.61,-4.445) B22(-1.88,-4.445) B23(-3.15,-4.445) B24(-4.42,-4.445) B25(-5.69,-4.445) B26(-6.96,-4.445) B27(-8.23,-4.445) B28(-9.5,-4.445) B29(-10.77,-4.445) B30(-12.04,-4.445) B31(-13.31,-4.445) B32(-14.58,-4.445) B33(-15.85,-4.445) B34(-17.12,-4.445) B35(-18.39,-4.445) B36(-19.66,-4.445) B37(-20.93,-4.445) B38(-22.2,-4.445) B39(-23.47,-4.445) B40(-24.74,-4.445) C1(24.79,-3.175) C2(23.52,-3.175) C3(22.25,-3.175) C4(20.98,-3.175) C5(19.71,-3.175) C6(18.44,-3.175) C7(17.17,-3.175) C8(15.9,-3.175) C9(14.63,-3.175) C10(13.36,-3.175) C11(12.09,-3.175) C12(10.82,-3.175) C13(9.55,-3.175) C14(8.28,-3.175) C15(7.01,-3.175) C16(5.74,-3.175) C17(4.47,-3.175) C18(3.2,-3.175) C19(1.93,-3.175) C20(0.66,-3.175) C21(-0.61,-3.175) C22(-1.88,-3.175) C23(-3.15,-3.175) C24(-4.42,-3.175) C25(-5.69,-3.175) C26(-6.96,-3.175) C27(-8.23,-3.175) C28(-9.5,-3.175) C29(-10.77,-3.175) C30(-12.04,-3.175) C31(-13.31,-3.175) C32(-14.58,-3.175) C33(-15.85,-3.175) C34(-17.12,-3.175) C35(-18.39,-3.175) C36(-19.66,-3.175) C37(-20.93,-3.175) C38(-22.2,-3.175) C39(-23.47,-3.175) C40(-24.74,-3.175) D1(24.79,-1.905) D2(23.52,-1.905) D3(22.25,-1.905) D4(20.98,-1.905) D5(19.71,-1.905) D6(18.44,-1.905) D7(17.17,-1.905) D8(15.9,-1.905) D9(14.63,-1.905) D10(13.36,-1.905) D11(12.09,-1.905) D12(10.82,-1.905) D13(9.55,-1.905) D14(8.28,-1.905) D15(7.01,-1.905) D16(5.74,-1.905) D17(4.47,-1.905) D18(3.2,-1.905) D19(1.93,-1.905) D20(0.66,-1.905) D21(-0.61,-1.905) D22(-1.88,-1.905) D23(-3.15,-1.905) D24(-4.42,-1.905) D25(-5.69,-1.905) D26(-6.96,-1.905) D27(-8.23,-1.905) D28(-9.5,-1.905) D29(-10.77,-1.905) D30(-12.04,-1.905) D31(-13.31,-1.905) D32(-14.58,-1.905) D33(-15.85,-1.905) D34(-17.12,-1.905) D35(-18.39,-1.905) D36(-19.66,-1.905) D37(-20.93,-1.905) D38(-22.2,-1.905) D39(-23.47,-1.905) D40(-24.74,-1.905) E1(24.79,-0.635) E2(23.52,-0.635) E3(22.25,-0.635) E4(20.98,-0.635) E5(19.71,-0.635) E6(18.44,-0.635) E7(17.17,-0.635) E8(15.9,-0.635) E9(14.63,-0.635) E10(13.36,-0.635) E11(12.09,-0.635) E12(10.82,-0.635) E13(9.55,-0.635) E14(8.28,-0.635) E15(7.01,-0.635) E16(5.74,-0.635) E17(4.47,-0.635) E18(3.2,-0.635) E19(1.93,-0.635) E20(0.66,-0.635) E21(-0.61,-0.635) E22(-1.88,-0.635) E23(-3.15,-0.635) E24(-4.42,-0.635) E25(-5.69,-0.635) E26(-6.96,-0.635) E27(-8.23,-0.635) E28(-9.5,-0.635) E29(-10.77,-0.635) E30(-12.04,-0.635) E31(-13.31,-0.635) E32(-14.58,-0.635) E33(-15.85,-0.635) E34(-17.12,-0.635) E35(-18.39,-0.635) E36(-19.66,-0.635) E37(-20.93,-0.635) E38(-22.2,-0.635) E39(-23.47,-0.635) E40(-24.74,-0.635) F1(24.79,0.635) F2(23.52,0.635) F3(22.25,0.635) F4(20.98,0.635) F5(19.71,0.635) F6(18.44,0.635) F7(17.17,0.635) F8(15.9,0.635) F9(14.63,0.635) F10(13.36,0.635) F11(12.09,0.635) F12(10.82,0.635) F13(9.55,0.635) F14(8.28,0.635) F15(7.01,0.635) F16(5.74,0.635) F17(4.47,0.635) F18(3.2,0.635) F19(1.93,0.635) F20(0.66,0.635) F21(-0.61,0.635) F22(-1.88,0.635) F23(-3.15,0.635) F24(-4.42,0.635) F25(-5.69,0.635) F26(-6.96,0.635) F27(-8.23,0.635) F28(-9.5,0.635) F29(-10.77,0.635) F30(-12.04,0.635) F31(-13.31,0.635) F32(-14.58,0.635) F33(-15.85,0.635) F34(-17.12,0.635) F35(-18.39,0.635) F36(-19.66,0.635) F37(-20.93,0.635) F38(-22.2,0.635) F39(-23.47,0.635) F40(-24.74,0.635) G1(24.79,1.905) G2(23.52,1.905) G3(22.25,1.905) G4(20.98,1.905) G5(19.71,1.905) G6(18.44,1.905) G7(17.17,1.905) G8(15.9,1.905) G9(14.63,1.905) G10(13.36,1.905) G11(12.09,1.905) G12(10.82,1.905) G13(9.55,1.905) G14(8.28,1.905) G15(7.01,1.905) G16(5.74,1.905) G17(4.47,1.905) G18(3.2,1.905) G19(1.93,1.905) G20(0.66,1.905) G21(-0.61,1.905) G22(-1.88,1.905) G23(-3.15,1.905) G24(-4.42,1.905) G25(-5.69,1.905) G26(-6.96,1.905) G27(-8.23,1.905) G28(-9.5,1.905) G29(-10.77,1.905) G30(-12.04,1.905) G31(-13.31,1.905) G32(-14.58,1.905) G33(-15.85,1.905) G34(-17.12,1.905) G35(-18.39,1.905) G36(-19.66,1.905) G37(-20.93,1.905) G38(-22.2,1.905) G39(-23.47,1.905) G40(-24.74,1.905) H1(24.79,3.175) H2(23.52,3.175) H3(22.25,3.175) H4(20.98,3.175) H5(19.71,3.175) H6(18.44,3.175) H7(17.17,3.175) H8(15.9,3.175) H9(14.63,3.175) H10(13.36,3.175) H11(12.09,3.175) H12(10.82,3.175) H13(9.55,3.175) H14(8.28,3.175) H15(7.01,3.175) H16(5.74,3.175) H17(4.47,3.175) H18(3.2,3.175) H19(1.93,3.175) H20(0.66,3.175) H21(-0.61,3.175) H22(-1.88,3.175) H23(-3.15,3.175) H24(-4.42,3.175) H25(-5.69,3.175) H26(-6.96,3.175) H27(-8.23,3.175) H28(-9.5,3.175) H29(-10.77,3.175) H30(-12.04,3.175) H31(-13.31,3.175) H32(-14.58,3.175) H33(-15.85,3.175) H34(-17.12,3.175) H35(-18.39,3.175) H36(-19.66,3.175) H37(-20.93,3.175) H38(-22.2,3.175) H39(-23.47,3.175) H40(-24.74,3.175) J1(24.79,4.445) J2(23.52,4.445) J3(22.25,4.445) J4(20.98,4.445) J5(19.71,4.445) J6(18.44,4.445) J7(17.17,4.445) J8(15.9,4.445) J9(14.63,4.445) J10(13.36,4.445) J11(12.09,4.445) J12(10.82,4.445) J13(9.55,4.445) J14(8.28,4.445) J15(7.01,4.445) J16(5.74,4.445) J17(4.47,4.445) J18(3.2,4.445) J19(1.93,4.445) J20(0.66,4.445) J21(-0.61,4.445) J22(-1.88,4.445) J23(-3.15,4.445) J24(-4.42,4.445) J25(-5.69,4.445) J26(-6.96,4.445) J27(-8.23,4.445) J28(-9.5,4.445) J29(-10.77,4.445) J30(-12.04,4.445) J31(-13.31,4.445) J32(-14.58,4.445) J33(-15.85,4.445) J34(-17.12,4.445) J35(-18.39,4.445) J36(-19.66,4.445) J37(-20.93,4.445) J38(-22.2,4.445) J39(-23.47,4.445) J40(-24.74,4.445) K1(24.79,5.715) K2(23.52,5.715) K3(22.25,5.715) K4(20.98,5.715) K5(19.71,5.715) K6(18.44,5.715) K7(17.17,5.715) K8(15.9,5.715) K9(14.63,5.715) K10(13.36,5.715) K11(12.09,5.715) K12(10.82,5.715) K13(9.55,5.715) K14(8.28,5.715) K15(7.01,5.715) K16(5.74,5.715) K17(4.47,5.715) K18(3.2,5.715) K19(1.93,5.715) K20(0.66,5.715) K21(-0.61,5.715) K22(-1.88,5.715) K23(-3.15,5.715) K24(-4.42,5.715) K25(-5.69,5.715) K26(-6.96,5.715) K27(-8.23,5.715) K28(-9.5,5.715) K29(-10.77,5.715) K30(-12.04,5.715) K31(-13.31,5.715) K32(-14.58,5.715) K33(-15.85,5.715) K34(-17.12,5.715) K35(-18.39,5.715) K36(-19.66,5.715) K37(-20.93,5.715) K38(-22.2,5.715) K39(-23.47,5.715) K40(-24.74,5.715)
  round 0 hole 2.69 unplated: ""(-31.471,2.007) ""(31.521,2.007)
  round 1.27 hole 1.27 unplated: ""(-27.166,3.05) ""(27.216,0)
  body extent -27.86,-7.34 28.81,7.34, height 7.11
SMBJ15CA [mil]
  rrect20% 85x107.99 smd: 1(-87.01,0) 2(87.01,0)
  silkscreen extent -125,-79 125,79, body extent -104,-73 104,73, height 89
SOD-123 [mm] "On Semi recommended land pattern"
  rect 0.915x1.22 smd: 1(-1.637,0) 2(1.637,0)
  silkscreen extent -2.74,-1.17 2.03,1.17, body extent -1.93,-0.9 1.93,0.9, height 1.35
SPC02SYAN [mil] "SULLINS"
  round 1 on Mech3: 0(0,0)
  body extent -98,-47 99,47, height 366
TDFN8 [mm]
  rrect30% 0.75x0.3 smd paste+0 mask+0.05: 1(-1.5,0.75) 2(-1.5,0.25) 3(-1.5,-0.25) 4(-1.5,-0.75) 5(1.478,-0.75) 6(1.478,-0.25) 7(1.478,0.25) 8(1.478,0.75)
  round 0.327 / inner round 0.454 / far side round 0.454 hole 0.2 mask+0.05: 9(-0.5,0) 9(0,-0.5) 9(0,0) 9(0,0.5) 9(0.5,0)
  rrect10% 1.36x1.46 smd paste+0 mask+0.05: 9(0,0)
  silkscreen extent -2.23,0.67 -2.14,0.83, body extent -1.5,-1 1.5,1, height 0.76
TI_Stacked_Overlay_Medium [mil]
  silkscreen extent -576,-136 576,135
WEEE_Minimum [mil] "WEEElie bin"
  silkscreen extent -95,-172 99,104
XGL4020 [mm]
  rrect10% 0.98x3.4 smd paste+0 mask+0: 1(-1.185,0) 2(1.185,0)
  silkscreen extent -2.67,-2.15 2.15,2.15, body extent -2.25,-2.25 2.25,2.25, height 0.25
YBG0006AJAP [mm] "DSBGA-6"
  round 0.23 smd paste-0.23 mask+0.032: A1(-0.2,0.4) A2(0.2,0.4) B1(-0.2,0) B2(0.2,0) C1(-0.2,-0.4) C2(0.2,-0.4)
  body extent -0.61,-0.81 0.62,0.82, height 0.5
YFF0012AKAD [mm] "TI DSBGA 1.675x1.418mm"
  round 0.225 smd paste-0.13 mask+0: A1(-0.4,0.6) A2(0,0.6) A3(0.4,0.6) B1(-0.4,0.2) B2(0,0.2) B3(0.4,0.2) C1(-0.4,-0.2) C2(0,-0.2) C3(0.4,-0.2) D1(-0.4,-0.6) D2(0,-0.6) D3(0.4,-0.6)
  silkscreen extent -0.8,-0.92 0.8,0.92, body extent -0.71,-0.84 0.71,0.84, height 0.63

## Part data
C1 C18 C32 C40 C51: library part capcc01380, "CAP CER 0.1UF 25V X7R 0402", Manufacturer="KYOCERA AVX", Operating Temperature="-55°C ~ 125°C", Ratings=-, Supplier Part Number 1=478-10050-1-ND, Temperature Coefficient=X7R, Tolerance=±5%, Voltage - Rated=25V
C2 C3 C4: library part capcc02687, "CAP CER 1UF 50V X7R 0805", Manufacturer="TDK Corporation", Operating Temperature="-55°C ~ 125°C", Ratings=-, Supplier Part Number 1=445-7547-1-ND, Temperature Coefficient=X7R, Tolerance=±10%, Voltage - Rated=50V
C5 C6: library part capcc03754, "CAP CER 1000PF 25V X7R 0201", Manufacturer="KYOCERA AVX", Operating Temperature="-55°C ~ 125°C", Ratings=-, Supplier Part Number 1=478-13000-1-ND, Temperature Coefficient=X7R, Tolerance=±10%, Voltage - Rated=25V
C7 C19 C52 C165 C177: library part capcc03511, "CAP CER 10UF 25V X7S 0805", Manufacturer="TDK Corporation", Operating Temperature="-55°C ~ 125°C", Ratings=-, Supplier Part Number 1=445-181600-1-ND, Temperature Coefficient=X7S, Tolerance=±10%, Voltage - Rated=25V
C8 C20 C53 C166 C178: library part capcc04216, "CAP CER 2200PF 50V X7R 0402", Manufacturer="KYOCERA AVX", Operating Temperature="-55°C ~ 125°C", Ratings=-, Supplier Part Number 1=478-5131-1-ND, Temperature Coefficient=X7R, Tolerance=±5%, Voltage - Rated=50V
C9 C10 C11 C12 C13 C14 C16 C17 C21 C22 C23 C24 C25 C41 C42 C43 C46 C54 C55 C56 C57: library part capcc09395, "CAP CER 22UF 10V X7S 0805", Manufacturer="TDK Corporation", Operating Temperature="-55°C ~ 125°C", Ratings=-, Supplier Part Number 1=445-14560-1-ND, Temperature Coefficient=X7S, Tolerance=±20%, Voltage - Rated=10V
C15: library part capcc02208, "CAP CER 0.47UF 16V X7S 0402", Manufacturer="TDK Corporation", Operating Temperature="-55°C ~ 125°C", Ratings=AEC-Q200, Supplier Part Number 1=445-174214-1-ND, Temperature Coefficient=X7S, Tolerance=±10%, Voltage - Rated=16V
C26 C28 C59 C65 C91 C109 C110 C114 C115 C120 C122 C123 C149: library part capcc09406, "CAP CER 10UF 10V X5R 0402", Manufacturer="KYOCERA AVX", Operating Temperature="-55°C ~ 85°C", Ratings=-, Supplier Part Number 1=478-10052-1-ND, Temperature Coefficient=X5R, Tolerance=±20%, Voltage - Rated=10V
C27 C35 C39 C60: library part capcc02785, "CAP CER 1UF 35V X5R 0402", Manufacturer="TDK Corporation", Operating Temperature="-55°C ~ 85°C", Ratings=-, Supplier Part Number 1=445-175218-1-ND, Temperature Coefficient=X5R, Tolerance=±10%, Voltage - Rated=35V
C29 C30 C33: library part capcc03154, "CAP CER 2.2UF 16V X6S 0402", Manufacturer="TDK Corporation", Operating Temperature="-55°C ~ 105°C", Ratings=-, Supplier Part Number 1=445-9103-1-ND, Temperature Coefficient=X6S, Tolerance=±10%, Voltage - Rated=16V
C31 C64: library part capcc03139, "CAP CER 4.7UF 10V X5R 0402", Manufacturer="TDK Corporation", Operating Temperature="-55°C ~ 85°C", Ratings=-, Supplier Part Number 1=445-175214-1-ND, Temperature Coefficient=X5R, Tolerance=±10%, Voltage - Rated=10V
C34: library part capcc05466, "CAP CER 10000PF 50V X7R 0402", Manufacturer="KYOCERA AVX", Operating Temperature="-55°C ~ 125°C", Ratings=-, Supplier Part Number 1=478-04025C103MAT2ACT-ND, Temperature Coefficient=X7R, Tolerance=±20%, Voltage - Rated=50V
C44 C45 C50 C67 C71 C76 C82 C92 C107 C108 C111 C112 C113 C116 C117 C118 C119 C121 C124 C125 C126 C127 C128 C129 C130 C131 C132 C139 C140 C141 C142 C143 C144 C145 C146 C147 C148 C150 C151 C152 C156 C159 C160 C164: library part capcc01294, "CAP CER 0.1UF 25V X5R 0201", Manufacturer="TDK Corporation", Operating Temperature="-55°C ~ 85°C", Ratings=-, Supplier Part Number 1=445-13671-1-ND, Temperature Coefficient=X5R, Tolerance=±10%, Voltage - Rated=25V
C68 C74 C75 C78 C79 C154 C155 C158: library part capcc08427, "CAP CER 68PF 25V C0G/NP0 0201", Manufacturer="Murata Electronics", Operating Temperature="-55°C ~ 125°C", Ratings=-, Supplier Part Number 1=490-13322-1-ND, Temperature Coefficient="C0G, NP0", Tolerance=±1%, Voltage - Rated=25V
C69 C70 C73 C80 C81 C84 C85 C86 C87 C88 C89 C90 C93 C94 C95 C96 C97 C98 C99 C100 C101 C102 C103 C104 C105 C106 C133 C134 C135 C136 C137 C138 C153: library part 0201RFCaps0693, "Broadband Capacitors", Alt Manufacturer="Murata Electronics", Alt PartNumber=GRM033C71C104ME14D, Manufacturer="Passive Plus", Operating Temperature="-55°C ~ 125°C", Temperature Coefficient="C0G, NP0", Tolerance=±10%, Voltage - Rated=16V
C72 C77 C83 C157: library part capcc06867, "CAP CER 0.6PF 50V C0G/NP0 0201", Manufacturer="Murata Electronics", Operating Temperature="-55°C ~ 125°C", Ratings=-, Supplier Part Number 1=490-17142-1-ND, Temperature Coefficient="C0G, NP0", Tolerance=±0.05pF, Voltage - Rated=50V
D1: library part cmp00440, "24.4V Clamp 24.6A Ipp Tvs Diode", Alt Manufacturer=-, Manufacturer=Littlefuse, Supplier Part Number 1=SMBJ15CALFCT-ND
D2: library part cmp00438, "DIODE SCHOTTKY 30V 1A SOD123", Alt Manufacturer="Rohm Semiconductor", Alt PartNumber=RB160M-30TR, Color=-, Manufacturer=Onsemi, Supplier Part Number 1=MBR130T1GOSCT-ND
D3: library part cmp00247, "LED GREEN CLEAR CHIP SMD", Alt Manufacturer=-, Color=Green, Current Rating (Amps)=20mA, Manufacturer="Lite-On Inc.", Supplier Part Number 1=160-1888-1-ND, Voltage - Forward (Vf) (Typ)=3.2V
FB1 FB2 FB3 FB4 FB5 FB6: library part dcp00004, "8.5 Ohms @ 100 MHz 1 Power Line Ferrite Bead 0603 (1608 Metric) 8A 4mOhm", Current=8A, Manufacturer=Murata, Operating Temperature="-55°C ~ 125°C", Supplier Part Number 1=490-BLE18PS080SN1DCT-ND, Temperature Coefficient=-
FC1 FC3 FC4 FC6: "Feed through capactior 27uF", Current=6A, Manufacturer=Murata, Operating Temperature="-40°C ~ 85°C", PartNumber=NFM31PC276B0J3L, Supplier Part Number 1=490-6984-1-ND, Temperature Coefficient=-, Tolerance=±20%, Voltage - Rated=6.3V
FID1 FID2 FID3: library part cmp00099, "Fiducial", Alt Manufacturer=-
H5 H6: library part cmp00097, "Hex Standoff Threaded #4-40 Stainless Steel 1.250\" (31.75mm) 1 1/4", Alt Manufacturer=-, Manufacturer="RAF Electronic Hardware", Supplier Part Number 1=1772-1827-ND
H7 H8: library part cmp00357, "Round Nylon Spacer 5.08mm", Alt Manufacturer=-, Manufacturer="Bivar Inc", Supplier Part Number 1=492-1767-ND
H9 H10: library part cmp00391, "Hex Nut 3/16\" Nylon 2-56", Alt Manufacturer=-, Manufacturer=McMaster-Carr
J1: "FMC, High Density Array, Male / EVM Connector 40x10", Alt Manufacturer=-, Manufacturer=Samtec, Supplier Part Number 1=SAM8730-ND
J2: "Power Jack, mini, 2.1mm OD, R/A, TH", Alt Manufacturer=-, Manufacturer=Switchcraft, Supplier Part Number 1=SC1313-ND
J3: library part cmp00061, "FTDI Dongle EVM Mating connector and standoff holes", Alt Manufacturer=-, Manufacturer=Samtec, Supplier Part Number 1=SAM8180-ND
J4 J5 J6: library part 132134-15, "SMA Connector Jack, Female Socket 50Ohm Surface Mount, Through Hole Solder", Alt Manufacturer=-, Manufacturer="Amphenol RF", Supplier Part Number 1=ACX1962-ND
J7 J8: "Header, 100mil, 2x1, Gold, TH", Alt Manufacturer="Sullins Connector Solutions", Alt PartNumber=PBC02SAAN, Color=-, Manufacturer=Samtec, Supplier Part Number 1=S1011E-02-ND
J9 J10: library part cmp00032, "SMP Connector Plug, Male Pin 50Ohm Surface Mount Solder", Alt Manufacturer=-, Manufacturer=Molex, Supplier Part Number 1=WM3891CT-ND, Voltage_V=335V
L7: library part LSMT56800072, "FIXED IND 1.5UH 11.1A 14.3 MOHM", Current - Saturation (Isat)=7.5A, Current Rating (Amps)="11.1 A", DC Resistance (DCR)="14.3mOhm Max", Frequency - Self Resonant=45MHz, Inductance="1.5 µH", Inductance Frequency - Test="1 MHz", Manufacturer=COILCRAFT, Operating Temperature="-40°C ~ 125°C", Q @ Freq=-, Ratings=AEC-Q200, Supplier Part Number 1=2457-XGL4020-152MEC-ND, Tolerance=±20%
LBL1: library part cmp00106, "Thermal Transfer Printable Labels, 0.650\" W x 0.200\" H - 10,000 per roll", Alt Manufacturer=-, Manufacturer=Brady, Supplier Part Number 1=2267-THT-14-423-10-ND
Logo1: library part cmp00104, "Texas Instrument Corporate Signature", Alt Manufacturer=-, PartNumber="TI Bug"
LOGO2: library part cmp00103, "CE_Mark", Alt Manufacturer=-
Logo3: library part CMP-0074847-1, "FCC_disclaimer"
Logo4: library part cmp00101, Alt Manufacturer=-, PartNumber=WEEE_Minimum
PP1 PP2 PP3 PP4 PP5 PP6 PP7 PP8 PP9 PP10 PP11 PP12 PP13 PP14 PP15 PP16 PP17 PP18 PP19 PP20 PP21 PP22 PP23 PP24 PP25 PP26 PP27 PP28 PP29 PP30 PP31: library part cmp00025, "Probe Point that can be used in lue of a test point", Alt Manufacturer=-
Q1: library part cmp00159, "MOSFET, N-CH, 20 V, 10 A", Alt Manufacturer=-, Manufacturer="Texas Instruments", Supplier Part Number 1=296-39992-1-ND
R1 R12 R20 R26 R32: library part OtherRs00002, "RES SHUNT, 0603, 0.002 OHM, 1%,", Manufacturer="Stackpole Electronics Inc", Operating Temperature="-55°C ~ 155°C", Power (Watts)=1/3W, Ratings=AEC-Q200, Resistance="2 mΩ", Supplier Part Number 1=738-CSS0603FT2L00CT-ND, Temperature Coefficient=±150ppm/°C, Tolerance=±1%
R2: library part RSMD020101018, "RES SMD 1M OHM 1% 1/20W 0201", Manufacturer="Panasonic Electronic Components", Operating Temperature="-55°C ~ 125°C", Power (Watts)="0.05W, 1/20W", Resistance="1 MΩ", Supplier Part Number 1=P122656CT-ND, Temperature Coefficient=±200ppm/°C, Tolerance=±1%
R3: library part RSMD020100623, "RES SMD 26.7K OHM 1% 1/20W 0201", Manufacturer="Panasonic Electronic Components", Operating Temperature="-55°C ~ 125°C", Power (Watts)="0.05W, 1/20W", Resistance="26.7 kΩ", Supplier Part Number 1=P122882CT-ND, Temperature Coefficient=±200ppm/°C, Tolerance=±1%
R4: library part RSMD040200945, "RES SMD 162K OHM 1% 1/10W 0402", Manufacturer="Panasonic Electronic Components", Operating Temperature="-55°C ~ 155°C", Power (Watts)="0.1W, 1/10W", Ratings=AEC-Q200, Resistance="162 kΩ", Supplier Part Number 1=P162KLCT-ND, Temperature Coefficient=±100ppm/°C, Tolerance=±1%
R5 R7 R75 R76 R78 R79 R181: library part RSMD040202616, "RES SMD 4.87K OHM 1% 1/10W 0402", Manufacturer="Panasonic Electronic Components", Operating Temperature="-55°C ~ 155°C", Power (Watts)="0.1W, 1/10W", Ratings=AEC-Q200, Resistance="4.87 kΩ", Supplier Part Number 1=P4.87KLCT-ND, Temperature Coefficient=±100ppm/°C, Tolerance=±1%
R6: library part RSMD040200802, "RES SMD 15.4KOHM 0.1% 1/16W 0402", Manufacturer="Panasonic Electronic Components", Operating Temperature="-55°C ~ 155°C", Power (Watts)="0.063W, 1/16W", Ratings=AEC-Q200, Resistance="15.4 kΩ", Supplier Part Number 1=P17733CT-ND, Temperature Coefficient=±15ppm/°C, Tolerance=±0.1%
R8 R11 R31: library part RSMD040202587, "RES SMD 4.7K OHM 1% 1/5W 0402", Manufacturer="Panasonic Electronic Components", Operating Temperature="-55°C ~ 155°C", Power (Watts)="0.2W, 1/5W", Ratings=AEC-Q200, Resistance="4.7 kΩ", Supplier Part Number 1=P17228CT-ND, Temperature Coefficient=±100ppm/°C, Tolerance=±1%
R9 R35: library part RSMD040203748, "RES SMD 80.6K OHM 1% 1/10W 0402", Manufacturer="Panasonic Electronic Components", Operating Temperature="-55°C ~ 155°C", Power (Watts)="0.1W, 1/10W", Ratings=AEC-Q200, Resistance="80.6 kΩ", Supplier Part Number 1=P80.6KLCT-ND, Temperature Coefficient=±100ppm/°C, Tolerance=±1%
R10 R19 R39: library part RSMD040202614, "RES SMD 4.87KOHM 0.1% 1/16W 0402", Manufacturer="Panasonic Electronic Components", Operating Temperature="-55°C ~ 155°C", Power (Watts)="0.063W, 1/16W", Ratings=AEC-Q200, Resistance="4.87 kΩ", Supplier Part Number 1=P17862CT-ND, Temperature Coefficient=±15ppm/°C, Tolerance=±0.1%
R13: library part CMP-0028070-1, "RES, 100, 1%, 0.05 W, 0201", Manufacturer="Yageo America", Power_W=50mW, Supplier Part Number 1=603-RC0201FS-7D100RL, TempCo="200 ppm/C", Tolerance_%=1%, Value2=0.05W, Value_Code=100R, ValueDisplayed=100
R14: library part RSMD040203578, "RES SMD 7.87KOHM 0.1% 1/16W 0402", Manufacturer="Panasonic Electronic Components", Operating Temperature="-55°C ~ 155°C", Power (Watts)="0.063W, 1/16W", Ratings=AEC-Q200, Resistance="7.87 kΩ", Supplier Part Number 1=P18115CT-ND, Temperature Coefficient=±10ppm/°C, Tolerance=±0.1%
R15: library part RSMD040201047, "RES SMD 18.2K OHM 1% 1/10W 0402", Manufacturer="Panasonic Electronic Components", Operating Temperature="-55°C ~ 155°C", Power (Watts)="0.1W, 1/10W", Ratings=AEC-Q200, Resistance="18.2 kΩ", Supplier Part Number 1=P18.2KLCT-ND, Temperature Coefficient=±100ppm/°C, Tolerance=±1%
R16: library part RSMD040203107, "RES SMD 54.9K OHM 1% 1/10W 0402", Manufacturer="Panasonic Electronic Components", Operating Temperature="-55°C ~ 155°C", Power (Watts)="0.1W, 1/10W", Ratings=AEC-Q200, Resistance="54.9 kΩ", Supplier Part Number 1=P54.9KLCT-ND, Temperature Coefficient=±100ppm/°C, Tolerance=±1%
R17: library part RSMD040203700, "RES SMD 8.06KOHM 0.1% 1/16W 0402", Manufacturer="Panasonic Electronic Components", Operating Temperature="-55°C ~ 155°C", Power (Watts)="0.063W, 1/16W", Ratings=AEC-Q200, Resistance="8.06 kΩ", Supplier Part Number 1=P17902CT-ND, Temperature Coefficient=±15ppm/°C, Tolerance=±0.1%
R18 R38: library part RSMD040200547, "RES SMD 12.4K OHM 1% 1/10W 0402", Manufacturer="Panasonic Electronic Components", Operating Temperature="-55°C ~ 155°C", Power (Watts)="0.1W, 1/10W", Ratings=AEC-Q200, Resistance="12.4 kΩ", Supplier Part Number 1=P12.4KLCT-ND, Temperature Coefficient=±100ppm/°C, Tolerance=±1%
R21 R34: library part RSMD040200444, "RES SMD 11.8KOHM 0.1% 1/16W 0402", Manufacturer="Panasonic Electronic Components", Operating Temperature="-55°C ~ 155°C", Power (Watts)="0.063W, 1/16W", Ratings=AEC-Q200, Resistance="11.8 kΩ", Supplier Part Number 1=10-ERA-2AEB1182XCT-ND, Temperature Coefficient=±25ppm/°C, Tolerance=±0.1%
R22: library part RSMD040201486, "RES SMD 22.6KOHM 0.1% 1/16W 0402", Manufacturer="Panasonic Electronic Components", Operating Temperature="-55°C ~ 155°C", Power (Watts)="0.063W, 1/16W", Ratings=AEC-Q200, Resistance="22.6 kΩ", Supplier Part Number 1=P17983CT-ND, Temperature Coefficient=±10ppm/°C, Tolerance=±0.1%
R23 R33 R100 R155: library part RSMD040201481, "RES SMD 22.1K OHM 1% 1/10W 0402", Manufacturer="Panasonic Electronic Components", Operating Temperature="-55°C ~ 155°C", Power (Watts)="0.1W, 1/10W", Ratings=AEC-Q200, Resistance="22.1 kΩ", Supplier Part Number 1=P22.1KLCT-ND, Temperature Coefficient=±100ppm/°C, Tolerance=±1%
